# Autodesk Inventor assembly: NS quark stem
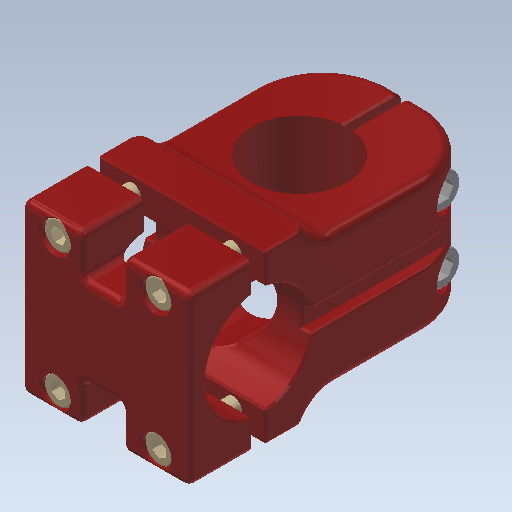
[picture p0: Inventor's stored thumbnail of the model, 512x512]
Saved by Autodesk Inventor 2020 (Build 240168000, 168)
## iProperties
Created: 2017-09
Part Number: NS quark stem
Material: Ogólny
Document SubType Name: Assembly
Designer: Tomasz
Sending System: SolidWorks 2017
Last Author: Tomasz
Last Saved: 2017-11-20
Author: Tomasz
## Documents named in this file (5)
- C:\Users\bruno\Documents\1-Cours-2020-21\1STI2D-2020-21\IT\6. Antivol\Inventor-Antivol\INVENTOR 2018_Steel Hardtail B+\NS quark stem.iam
- C:\Users\bruno\Documents\1-Cours-2020-21\1STI2D-2020-21\IT\6. Antivol\Inventor-Antivol\INVENTOR 2018_Steel Hardtail B+\NS QUARK.ipt
- C:\Users\bruno\Documents\1-Cours-2020-21\1STI2D-2020-21\IT\6. Antivol\Inventor-Antivol\INVENTOR 2018_Steel Hardtail B+\pokrywa NS Quark.ipt
- C:\Users\bruno\Documents\1-Cours-2020-21\1STI2D-2020-21\IT\6. Antivol\Inventor-Antivol\INVENTOR 2018_Steel Hardtail B+\ISO 4762 - M5 x 25ISO.ipt
- C:\Users\bruno\Documents\1-Cours-2020-21\1STI2D-2020-21\IT\6. Antivol\Inventor-Antivol\INVENTOR 2018_Steel Hardtail B+\ISO 4762 - M6 x 30ISO.ipt
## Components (8 placed, 4 different names)
1. NS QUARK:1
2. pokrywa NS Quark:1
3. ISO 4762 - M5 x 25ISO:1
4. ISO 4762 - M5 x 25ISO:2
5. ISO 4762 - M5 x 25ISO:3
6. ISO 4762 - M5 x 25ISO:4
7. ISO 4762 - M6 x 30ISO:1
8. ISO 4762 - M6 x 30ISO:2
